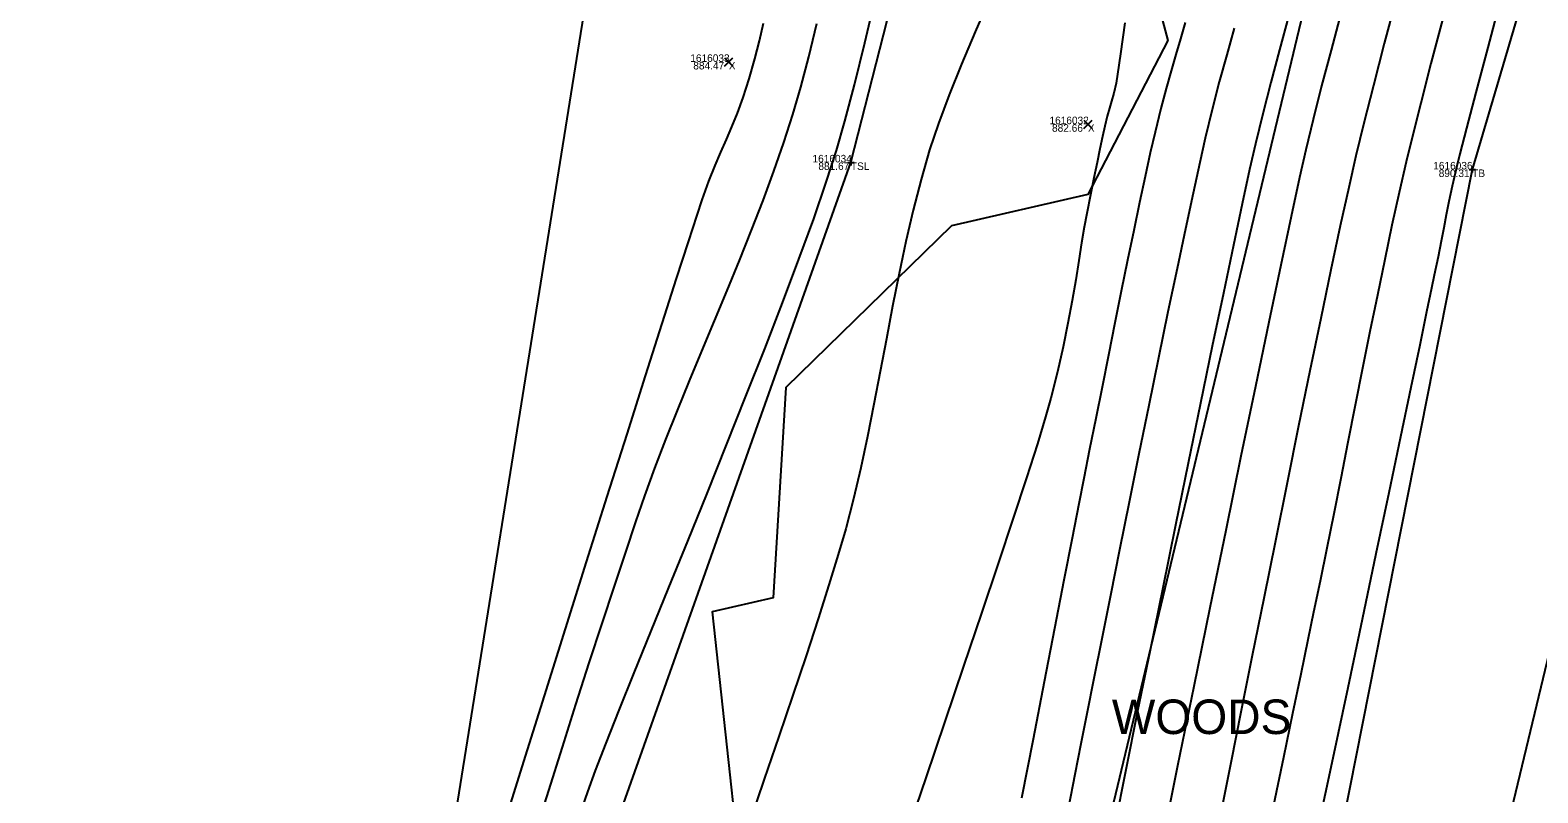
# Model space of a CAD drawing. Extents: x 1957117 to 1971063, y 701601 to 715861.
# Drawn here: x 1963119.1 to 1963189, y 705478.1 to 705513.5 of the extents above; entities that cross this region are included whole.
import ezdxf

# ---------------------------------------------------------------- set-up
doc = ezdxf.new("R2010")
doc.units = 0
for name, color, linetype in [('AP_X_Lights', 7, 'Continuous'), ('DT_X_Break_Line', 7, 'Continuous'), ('DT_X_Contour_Major', 7, 'Continuous'), ('DT_X_Contour_Minor', 7, 'Continuous'), ('DT_X_TIN_Hull', 7, 'Continuous'), ('GE_X_CL_20', 7, 'Continuous'), ('HY_X_Water_Edge', 7, 'Continuous'), ('PV_P_Drive', 7, 'Continuous'), ('PV_P_Shoulder', 7, 'Continuous'), ('RS_Raster1', 7, 'Continuous'), ('RW_X_Esmt_RR', 7, 'Continuous'), ('SC_Scratch1', 7, 'Continuous'), ('SC_Shading5', 7, 'Continuous'), ('VG_X_Text', 7, 'Continuous'), ('VG_X_Tree_Line_Rt', 7, 'Continuous')]:
    doc.layers.add(name, color=color, linetype=linetype)

msp = doc.modelspace()

# ---------------------------------------------------------------- linework, layer by layer
at = {"layer": 'AP_X_Lights'}
for p, q in [((1963151.267, 705511.808), (1963151.655, 705512.198)), ((1963151.267, 705512.198), (1963151.655, 705511.808)), ((1963167.911, 705508.92), (1963168.299, 705509.31)), ((1963167.911, 705509.31), (1963168.299, 705508.92))]:
    msp.add_line(p, q, dxfattribs=at)
at = {"layer": 'DT_X_Break_Line'}
for points in [[(1963059.618, 705072.384), (1963067.267, 705121.949), (1963084.435, 705172.155), (1963089.948, 705219.61), (1963104.733, 705267.194), (1963118.935, 705315.406), (1963122.413, 705362.88), (1963135.773, 705414.457), (1963142.701, 705466.671), (1963157.121, 705507.344), (1963171.033, 705561.75), (1963190.964, 705600.578), (1963199.065, 705656.682), (1963210.848, 705704.455), (1963218.329, 705756.178)], [(1963248.355, 705747.376), (1963235.759, 705698.829), (1963221.229, 705652.053), (1963207.844, 705601.615), (1963200.47, 705556.329), (1963185.917, 705507.018), (1963175.154, 705452.621), (1963160.398, 705408.434), (1963150.566, 705354.43), (1963137.351, 705306.484), (1963127.753, 705261.545), (1963117.087, 705216.019), (1963104.746, 705164.3), (1963091.28, 705116.393), (1963081.686, 705067.168)]]:
    msp.add_lwpolyline(points, dxfattribs=at)
at = {"layer": 'DT_X_Contour_Major'}
for points in [[(1963187.276, 705515.099), (1963186.634, 705512.668), (1963186.087, 705510.589), (1963185.652, 705508.927), (1963185.346, 705507.744), (1963185.186, 705507.104), (1963184.992, 705506.251), (1963184.84, 705505.539), (1963184.714, 705504.913), (1963184.599, 705504.314), (1963184.479, 705503.687), (1963184.338, 705502.973), (1963184.161, 705502.115), (1963184.035, 705501.516), (1963183.806, 705500.416), (1963183.483, 705498.867), (1963183.077, 705496.92), (1963182.597, 705494.625), (1963182.054, 705492.034), (1963181.458, 705489.197), (1963180.819, 705486.167), (1963180.148, 705482.994), (1963179.454, 705479.728), (1963178.747, 705476.422)], [(1963187.276, 705515.099), (1963186.634, 705512.668), (1963186.087, 705510.589), (1963185.652, 705508.927), (1963185.346, 705507.744), (1963185.186, 705507.104), (1963184.992, 705506.251), (1963184.84, 705505.539), (1963184.714, 705504.913), (1963184.599, 705504.314), (1963184.479, 705503.687), (1963184.338, 705502.973), (1963184.161, 705502.115), (1963184.035, 705501.516), (1963183.806, 705500.416), (1963183.483, 705498.867), (1963183.077, 705496.92), (1963182.597, 705494.625), (1963182.054, 705492.034), (1963181.458, 705489.197), (1963180.819, 705486.167), (1963180.148, 705482.994), (1963179.454, 705479.728), (1963178.747, 705476.422)], [(1963174.884, 705513.571), (1963174.538, 705512.335), (1963174.197, 705511.079), (1963173.864, 705509.795), (1963173.544, 705508.475), (1963173.286, 705507.339), (1963172.977, 705505.925), (1963172.624, 705504.273), (1963172.236, 705502.423), (1963171.818, 705500.414), (1963171.381, 705498.287), (1963170.93, 705496.081), (1963170.474, 705493.836), (1963170.02, 705491.593), (1963169.576, 705489.391), (1963169.15, 705487.269), (1963168.749, 705485.269), (1963168.381, 705483.43), (1963168.054, 705481.792), (1963167.775, 705480.394), (1963167.496, 705478.982), (1963167.203, 705477.465)], [(1963174.884, 705513.571), (1963174.538, 705512.335), (1963174.197, 705511.079), (1963173.864, 705509.795), (1963173.544, 705508.475), (1963173.286, 705507.339), (1963172.977, 705505.925), (1963172.624, 705504.273), (1963172.236, 705502.423), (1963171.818, 705500.414), (1963171.381, 705498.287), (1963170.93, 705496.081), (1963170.474, 705493.836), (1963170.02, 705491.593), (1963169.576, 705489.391), (1963169.15, 705487.269), (1963168.749, 705485.269), (1963168.381, 705483.43), (1963168.054, 705481.792), (1963167.775, 705480.394), (1963167.496, 705478.982), (1963167.203, 705477.465)]]:
    msp.add_lwpolyline(points, dxfattribs=at)
at = {"layer": 'DT_X_Contour_Minor'}
for points in [[(1963144.476, 705476.892), (1963144.925, 705478.179), (1963145.287, 705479.164), (1963145.777, 705480.434), (1963146.38, 705481.952), (1963147.076, 705483.682), (1963147.849, 705485.589), (1963148.682, 705487.636), (1963149.556, 705489.786), (1963150.456, 705492.006), (1963151.362, 705494.257), (1963152.259, 705496.504), (1963153.128, 705498.712), (1963153.952, 705500.844), (1963154.714, 705502.864), (1963155.396, 705504.737), (1963155.982, 705506.425), (1963156.453, 705507.894), (1963156.843, 705509.26), (1963157.282, 705510.938), (1963157.763, 705512.886), (1963158.278, 705515.063)], [(1963144.476, 705476.892), (1963144.925, 705478.179), (1963145.287, 705479.164), (1963145.777, 705480.434), (1963146.38, 705481.952), (1963147.076, 705483.682), (1963147.849, 705485.589), (1963148.682, 705487.636), (1963149.556, 705489.786), (1963150.456, 705492.006), (1963151.362, 705494.257), (1963152.259, 705496.504), (1963153.128, 705498.712), (1963153.952, 705500.844), (1963154.714, 705502.864), (1963155.396, 705504.737), (1963155.982, 705506.425), (1963156.453, 705507.894), (1963156.843, 705509.26), (1963157.282, 705510.938), (1963157.763, 705512.886), (1963158.278, 705515.063)], [(1963163.555, 705514.967), (1963162.876, 705513.403), (1963162.244, 705511.9), (1963161.671, 705510.476), (1963161.174, 705509.148), (1963160.768, 705507.932), (1963160.371, 705506.559), (1963160.007, 705505.138), (1963159.671, 705503.68), (1963159.356, 705502.193), (1963159.056, 705500.687), (1963158.766, 705499.17), (1963158.478, 705497.651), (1963158.189, 705496.141), (1963157.89, 705494.648), (1963157.577, 705493.182), (1963157.243, 705491.75), (1963156.882, 705490.364), (1963156.535, 705489.165), (1963156.105, 705487.766), (1963155.603, 705486.195), (1963155.041, 705484.481), (1963154.43, 705482.65), (1963153.781, 705480.733), (1963153.107, 705478.756), (1963152.419, 705476.75)], [(1963163.555, 705514.967), (1963162.876, 705513.403), (1963162.244, 705511.9), (1963161.671, 705510.476), (1963161.174, 705509.148), (1963160.768, 705507.932), (1963160.371, 705506.559), (1963160.007, 705505.138), (1963159.671, 705503.68), (1963159.356, 705502.193), (1963159.056, 705500.687), (1963158.766, 705499.17), (1963158.478, 705497.651), (1963158.189, 705496.141), (1963157.89, 705494.648), (1963157.577, 705493.182), (1963157.243, 705491.75), (1963156.882, 705490.364), (1963156.535, 705489.165), (1963156.105, 705487.766), (1963155.603, 705486.195), (1963155.041, 705484.481), (1963154.43, 705482.65), (1963153.781, 705480.733), (1963153.107, 705478.756), (1963152.419, 705476.75)], [(1963182.393, 705514.946), (1963181.839, 705512.853), (1963181.336, 705510.916), (1963180.895, 705509.171), (1963180.529, 705507.652), (1963180.194, 705506.176), (1963179.804, 705504.398), (1963179.37, 705502.361), (1963178.897, 705500.109), (1963178.396, 705497.685), (1963177.872, 705495.132), (1963177.335, 705492.493), (1963176.793, 705489.811), (1963176.253, 705487.13), (1963175.723, 705484.493), (1963175.211, 705481.943), (1963174.726, 705479.523), (1963174.275, 705477.277)], [(1963182.393, 705514.946), (1963181.839, 705512.853), (1963181.336, 705510.916), (1963180.895, 705509.171), (1963180.529, 705507.652), (1963180.194, 705506.176), (1963179.804, 705504.398), (1963179.37, 705502.361), (1963178.897, 705500.109), (1963178.396, 705497.685), (1963177.872, 705495.132), (1963177.335, 705492.493), (1963176.793, 705489.811), (1963176.253, 705487.13), (1963175.723, 705484.493), (1963175.211, 705481.943), (1963174.726, 705479.523), (1963174.275, 705477.277)], [(1963141.052, 705476.656), (1963141.965, 705479.574), (1963142.92, 705482.618), (1963143.897, 705485.724), (1963144.874, 705488.825), (1963145.83, 705491.857), (1963146.746, 705494.752), (1963147.6, 705497.447), (1963148.372, 705499.875), (1963149.042, 705501.971), (1963149.588, 705503.669), (1963149.989, 705504.905), (1963150.226, 705505.611), (1963150.542, 705506.472), (1963150.831, 705507.194), (1963151.1, 705507.823), (1963151.357, 705508.408), (1963151.608, 705508.993), (1963151.862, 705509.627), (1963152.125, 705510.356), (1963152.404, 705511.226), (1963152.666, 705512.14), (1963152.881, 705512.987), (1963153.064, 705513.802)], [(1963141.052, 705476.656), (1963141.965, 705479.574), (1963142.92, 705482.618), (1963143.897, 705485.724), (1963144.874, 705488.825), (1963145.83, 705491.857), (1963146.746, 705494.752), (1963147.6, 705497.447), (1963148.372, 705499.875), (1963149.042, 705501.971), (1963149.588, 705503.669), (1963149.989, 705504.905), (1963150.226, 705505.611), (1963150.542, 705506.472), (1963150.831, 705507.194), (1963151.1, 705507.823), (1963151.357, 705508.408), (1963151.608, 705508.993), (1963151.862, 705509.627), (1963152.125, 705510.356), (1963152.404, 705511.226), (1963152.666, 705512.14), (1963152.881, 705512.987), (1963153.064, 705513.802)], [(1963142.491, 705476.237), (1963143.117, 705478.24), (1963143.749, 705480.245), (1963144.379, 705482.223), (1963144.997, 705484.145), (1963145.593, 705485.981), (1963146.158, 705487.704), (1963146.683, 705489.283), (1963147.159, 705490.69), (1963147.575, 705491.895), (1963148.041, 705493.178), (1963148.546, 705494.497), (1963149.082, 705495.845), (1963149.642, 705497.216), (1963150.217, 705498.604), (1963150.8, 705500.002), (1963151.383, 705501.405), (1963151.958, 705502.806), (1963152.516, 705504.198), (1963153.05, 705505.576), (1963153.552, 705506.933), (1963154.015, 705508.263), (1963154.429, 705509.56), (1963154.793, 705510.828), (1963155.165, 705512.244), (1963155.543, 705513.784)], [(1963142.491, 705476.237), (1963143.117, 705478.24), (1963143.749, 705480.245), (1963144.379, 705482.223), (1963144.997, 705484.145), (1963145.593, 705485.981), (1963146.158, 705487.704), (1963146.683, 705489.283), (1963147.159, 705490.69), (1963147.575, 705491.895), (1963148.041, 705493.178), (1963148.546, 705494.497), (1963149.082, 705495.845), (1963149.642, 705497.216), (1963150.217, 705498.604), (1963150.8, 705500.002), (1963151.383, 705501.405), (1963151.958, 705502.806), (1963152.516, 705504.198), (1963153.05, 705505.576), (1963153.552, 705506.933), (1963154.015, 705508.263), (1963154.429, 705509.56), (1963154.793, 705510.828), (1963155.165, 705512.244), (1963155.543, 705513.784)], [(1963169.825, 705513.81), (1963169.618, 705512.384), (1963169.477, 705511.436), (1963169.41, 705511.019), (1963169.304, 705510.553), (1963169.206, 705510.186), (1963169.108, 705509.853), (1963169.004, 705509.487), (1963168.887, 705509.023), (1963168.778, 705508.539), (1963168.659, 705507.978), (1963168.529, 705507.342), (1963168.386, 705506.631), (1963168.229, 705505.845), (1963168.057, 705504.984), (1963167.938, 705504.34), (1963167.816, 705503.61), (1963167.685, 705502.796), (1963167.54, 705501.903), (1963167.374, 705500.937), (1963167.183, 705499.9), (1963166.96, 705498.798), (1963166.699, 705497.635), (1963166.395, 705496.415), (1963166.148, 705495.55), (1963165.762, 705494.305), (1963165.254, 705492.727), (1963164.642, 705490.86), (1963163.942, 705488.752), (1963163.17, 705486.449), (1963162.343, 705483.995), (1963161.477, 705481.437), (1963160.59, 705478.821), (1963159.698, 705476.193)], [(1963169.825, 705513.81), (1963169.618, 705512.384), (1963169.477, 705511.436), (1963169.41, 705511.019), (1963169.304, 705510.553), (1963169.206, 705510.186), (1963169.108, 705509.853), (1963169.004, 705509.487), (1963168.887, 705509.023), (1963168.778, 705508.539), (1963168.659, 705507.978), (1963168.529, 705507.342), (1963168.386, 705506.631), (1963168.229, 705505.845), (1963168.057, 705504.984), (1963167.938, 705504.34), (1963167.816, 705503.61), (1963167.685, 705502.796), (1963167.54, 705501.903), (1963167.374, 705500.937), (1963167.183, 705499.9), (1963166.96, 705498.798), (1963166.699, 705497.635), (1963166.395, 705496.415), (1963166.148, 705495.55), (1963165.762, 705494.305), (1963165.254, 705492.727), (1963164.642, 705490.86), (1963163.942, 705488.752), (1963163.17, 705486.449), (1963162.343, 705483.995), (1963161.477, 705481.437), (1963160.59, 705478.821), (1963159.698, 705476.193)], [(1963172.61, 705513.834), (1963172.395, 705513.078), (1963172.179, 705512.346), (1963171.958, 705511.591), (1963171.727, 705510.77), (1963171.481, 705509.838), (1963171.216, 705508.749), (1963170.997, 705507.789), (1963170.757, 705506.695), (1963170.499, 705505.488), (1963170.227, 705504.185), (1963169.943, 705502.808), (1963169.652, 705501.374), (1963169.355, 705499.904), (1963169.057, 705498.418), (1963168.761, 705496.933), (1963168.47, 705495.471), (1963168.187, 705494.05), (1963167.916, 705492.689), (1963167.685, 705491.522), (1963167.373, 705489.933), (1963166.993, 705487.985), (1963166.556, 705485.741), (1963166.075, 705483.265), (1963165.563, 705480.621), (1963165.03, 705477.872)], [(1963172.61, 705513.834), (1963172.395, 705513.078), (1963172.179, 705512.346), (1963171.958, 705511.591), (1963171.727, 705510.77), (1963171.481, 705509.838), (1963171.216, 705508.749), (1963170.997, 705507.789), (1963170.757, 705506.695), (1963170.499, 705505.488), (1963170.227, 705504.185), (1963169.943, 705502.808), (1963169.652, 705501.374), (1963169.355, 705499.904), (1963169.057, 705498.418), (1963168.761, 705496.933), (1963168.47, 705495.471), (1963168.187, 705494.05), (1963167.916, 705492.689), (1963167.685, 705491.522), (1963167.373, 705489.933), (1963166.993, 705487.985), (1963166.556, 705485.741), (1963166.075, 705483.265), (1963165.563, 705480.621), (1963165.03, 705477.872)], [(1963177.41, 705514.114), (1963176.985, 705512.562), (1963176.583, 705511.05), (1963176.21, 705509.593), (1963175.872, 705508.201), (1963175.603, 705507.009), (1963175.258, 705505.426), (1963174.848, 705503.502), (1963174.383, 705501.288), (1963173.872, 705498.834), (1963173.326, 705496.19), (1963172.754, 705493.408), (1963172.167, 705490.538), (1963171.574, 705487.63), (1963170.986, 705484.735), (1963170.412, 705481.904), (1963169.863, 705479.186), (1963169.348, 705476.632)], [(1963177.41, 705514.114), (1963176.985, 705512.562), (1963176.583, 705511.05), (1963176.21, 705509.593), (1963175.872, 705508.201), (1963175.603, 705507.009), (1963175.258, 705505.426), (1963174.848, 705503.502), (1963174.383, 705501.288), (1963173.872, 705498.834), (1963173.326, 705496.19), (1963172.754, 705493.408), (1963172.167, 705490.538), (1963171.574, 705487.63), (1963170.986, 705484.735), (1963170.412, 705481.904), (1963169.863, 705479.186), (1963169.348, 705476.632)], [(1963179.845, 705514.305), (1963179.373, 705512.551), (1963178.936, 705510.889), (1963178.542, 705509.34), (1963178.201, 705507.926), (1963177.911, 705506.642), (1963177.521, 705504.841), (1963177.042, 705502.586), (1963176.488, 705499.94), (1963175.869, 705496.966), (1963175.2, 705493.726), (1963174.493, 705490.285), (1963173.759, 705486.704), (1963173.012, 705483.047), (1963172.264, 705479.377), (1963171.528, 705475.757)], [(1963179.845, 705514.305), (1963179.373, 705512.551), (1963178.936, 705510.889), (1963178.542, 705509.34), (1963178.201, 705507.926), (1963177.911, 705506.642), (1963177.521, 705504.841), (1963177.042, 705502.586), (1963176.488, 705499.94), (1963175.869, 705496.966), (1963175.2, 705493.726), (1963174.493, 705490.285), (1963173.759, 705486.704), (1963173.012, 705483.047), (1963172.264, 705479.377), (1963171.528, 705475.757)], [(1963184.556, 705514.014), (1963184.007, 705511.927), (1963183.533, 705510.095), (1963183.145, 705508.564), (1963182.858, 705507.378), (1963182.531, 705505.947), (1963182.198, 705504.43), (1963181.861, 705502.841), (1963181.521, 705501.198), (1963181.179, 705499.515), (1963180.837, 705497.809), (1963180.496, 705496.093), (1963180.159, 705494.386), (1963179.826, 705492.701), (1963179.498, 705491.054), (1963179.179, 705489.462), (1963178.868, 705487.939), (1963178.568, 705486.502), (1963178.298, 705485.213), (1963177.969, 705483.634), (1963177.59, 705481.804), (1963177.167, 705479.766), (1963176.709, 705477.56)], [(1963184.556, 705514.014), (1963184.007, 705511.927), (1963183.533, 705510.095), (1963183.145, 705508.564), (1963182.858, 705507.378), (1963182.531, 705505.947), (1963182.198, 705504.43), (1963181.861, 705502.841), (1963181.521, 705501.198), (1963181.179, 705499.515), (1963180.837, 705497.809), (1963180.496, 705496.093), (1963180.159, 705494.386), (1963179.826, 705492.701), (1963179.498, 705491.054), (1963179.179, 705489.462), (1963178.868, 705487.939), (1963178.568, 705486.502), (1963178.298, 705485.213), (1963177.969, 705483.634), (1963177.59, 705481.804), (1963177.167, 705479.766), (1963176.709, 705477.56)]]:
    msp.add_lwpolyline(points, dxfattribs=at)
at = {"layer": 'DT_X_TIN_Hull'}
msp.add_lwpolyline([(1963254.734, 705951.873), (1963238.207, 705904.757), (1963226.355, 705855.27), (1963191.43, 705709.793), (1963179.827, 705661.653), (1963168.092, 705612.411), (1963156.438, 705563.606), (1963144.855, 705514.97), (1963136.901, 705465.31), (1963121.943, 705418.117), (1963098.235, 705321.162), (1963062.2, 705175.46), (1963037.999, 705077.244)], dxfattribs=at)
at = {"layer": 'GE_X_CL_20'}
msp.add_lwpolyline([(1963418.3, 706437.397), (1962895.621, 704261.062)], dxfattribs=at)
at = {"layer": 'HY_X_Water_Edge'}
msp.add_spline([(1963191.723, 701994.048), (1963062.047, 702441.167), (1962863.491, 703169.356), (1962827.53, 703438.691), (1962823.213, 703537.412), (1962817.962, 703593.874), (1962817.97, 703697.316), (1962828.582, 703804.235), (1962836.461, 703844.734), (1962850.687, 703896.004), (1962867.251, 703938.846), (1962873.848, 703992.355), (1962884.135, 704091.371), (1962891.241, 704140.854), (1962897.382, 704180.529), (1962905.467, 704230.979), (1962943.949, 704328.022), (1962948.537, 704378.842), (1962964.114, 704426.264), (1963004.885, 704570.73), (1963042.054, 704716.522), (1963062.038, 704814.417), (1963072.171, 704860.237), (1963090.023, 704956.798), (1963107.066, 705031.783), (1963133.773, 705105.742), (1963148.685, 705206.74), (1963175.48, 705301.059), (1963191.635, 705353.417), (1963210.988, 705447.286), (1963219.532, 705497.27), (1963230.124, 705549.475), (1963251.052, 705591.159), (1963275.289, 705693.429), (1963292.982, 705784.032), (1963302.841, 705839.645), (1963335.126, 705936.766), (1963359.752, 706046.75), (1963389.133, 706177.299), (1963417.827, 706273.456), (1963475.868, 706451.902), (1963533.782, 706640.53), (1963553.86, 706696.984), (1963580.184, 706715.425), (1963609.172, 706718.73), (1963617.062, 706714.691), (1963619.447, 706694.678), (1963564.282, 706533.07), (1963531.853, 706395.229), (1963434.4, 706006.96), (1963354.09, 705679.186), (1963237.513, 705206.07), (1963167.369, 704892.962), (1963059.145, 704434.176), (1962907.914, 703908.742), (1962877.458, 703703.326), (1962898.357, 703412.121), (1962942.65, 703052.267), (1963048.963, 702674.866), (1963191.468, 702189.666), (1963245.396, 702019.832)], degree=3, dxfattribs=at)
at = {"layer": 'PV_P_Drive'}
for p, q in [((1963157.121, 705507.49), (1963157.121, 705507.198)), ((1963156.975, 705507.344), (1963157.267, 705507.344)), ((1963157.121, 705507.344), (1963157.121, 705507.344)), ((1963185.771, 705507.018), (1963186.063, 705507.018)), ((1963185.917, 705507.164), (1963185.917, 705506.872)), ((1963185.917, 705507.018), (1963185.917, 705507.018))]:
    msp.add_line(p, q, dxfattribs=at)
at = {"layer": 'RW_X_Esmt_RR'}
msp.add_lwpolyline([(1962866.45, 704268.068), (1963123.345, 705337.727), (1963135.496, 705336.937), (1963400.797, 706441.601)], dxfattribs=at)
at = {"layer": 'SC_Shading5'}
for points in [[(1963026.912, 704294.121), (1963138.818, 704737.794), (1963251.679, 705213.963), (1963374.306, 705730.111), (1963454.783, 706045.593), (1963517.244, 706296.713), (1963562.763, 706479.256), (1963580.13, 706553.799), (1963589.678, 706586.994)], [(1963609.915, 706579.703), (1963587.283, 706499.153), (1963552.056, 706354.005), (1963480.911, 706069.234), (1963357.401, 705576.869), (1963272.751, 705226.931), (1963210.247, 704956.481), (1963044.97, 704288.881)]]:
    msp.add_spline(points, degree=3, dxfattribs=at)
at = {"layer": 'VG_X_Tree_Line_Rt'}
msp.add_lwpolyline([(1963170.042, 705519.614), (1963171.809, 705512.992), (1963168.095, 705505.86), (1963161.791, 705504.406), (1963154.098, 705496.914), (1963153.517, 705487.162), (1963150.697, 705486.514), (1963152.535, 705469.552), (1963155.104, 705460.385), (1963159.499, 705453.167), (1963159.333, 705449.02), (1963157.482, 705445.047), (1963153.748, 705444.038), (1963148.585, 705442.756), (1963145.334, 705438.187), (1963140.979, 705435.891), (1963136.507, 705437.977), (1963129.733, 705432.733), (1963125.595, 705427.896), (1963128.863, 705421.23), (1963129.219, 705409.143)], dxfattribs=at)

# ---------------------------------------------------------------- texts
at = {"layer": 'PV_P_Shoulder'}
for s, p in [('884.47', (1963149.816, 705511.653)), ('882.66', (1963166.443, 705508.765)), ('881.67', (1963155.614, 705506.994)), ('890.31', (1963184.365, 705506.668))]:
    msp.add_text(s, height=0.35, dxfattribs=at).set_placement(p)
at = {"layer": 'RS_Raster1'}
for s, p in [('1616033', (1963149.678, 705512.003)), ('1616032', (1963166.325, 705509.115)), ('1616034', (1963155.341, 705507.344)), ('1616036', (1963184.112, 705507.018))]:
    msp.add_text(s, height=0.35, dxfattribs=at).set_placement(p)
at = {"layer": 'SC_Scratch1'}
for s, p in [('X', (1963151.461, 705511.653)), ('X', (1963168.105, 705508.765)), ('TSL', (1963157.121, 705506.994)), ('TB', (1963185.917, 705506.668))]:
    msp.add_text(s, height=0.35, dxfattribs=at).set_placement(p)
at = {"layer": 'VG_X_Text'}
msp.add_text('WOODS', height=1.6, dxfattribs=at).set_placement((1963169.214, 705480.851))

doc.saveas('drawing.dxf')
